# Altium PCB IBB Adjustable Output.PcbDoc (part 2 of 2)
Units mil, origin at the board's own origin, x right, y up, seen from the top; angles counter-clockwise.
Board outline 3000 x 2700 mil, 4 copper layers (Top Layer, Signal Layer 1, Signal Layer 2, Bottom Layer), stack 61.2 mil thick; 75 components, 28 nets, 136 pads, 154 vias.
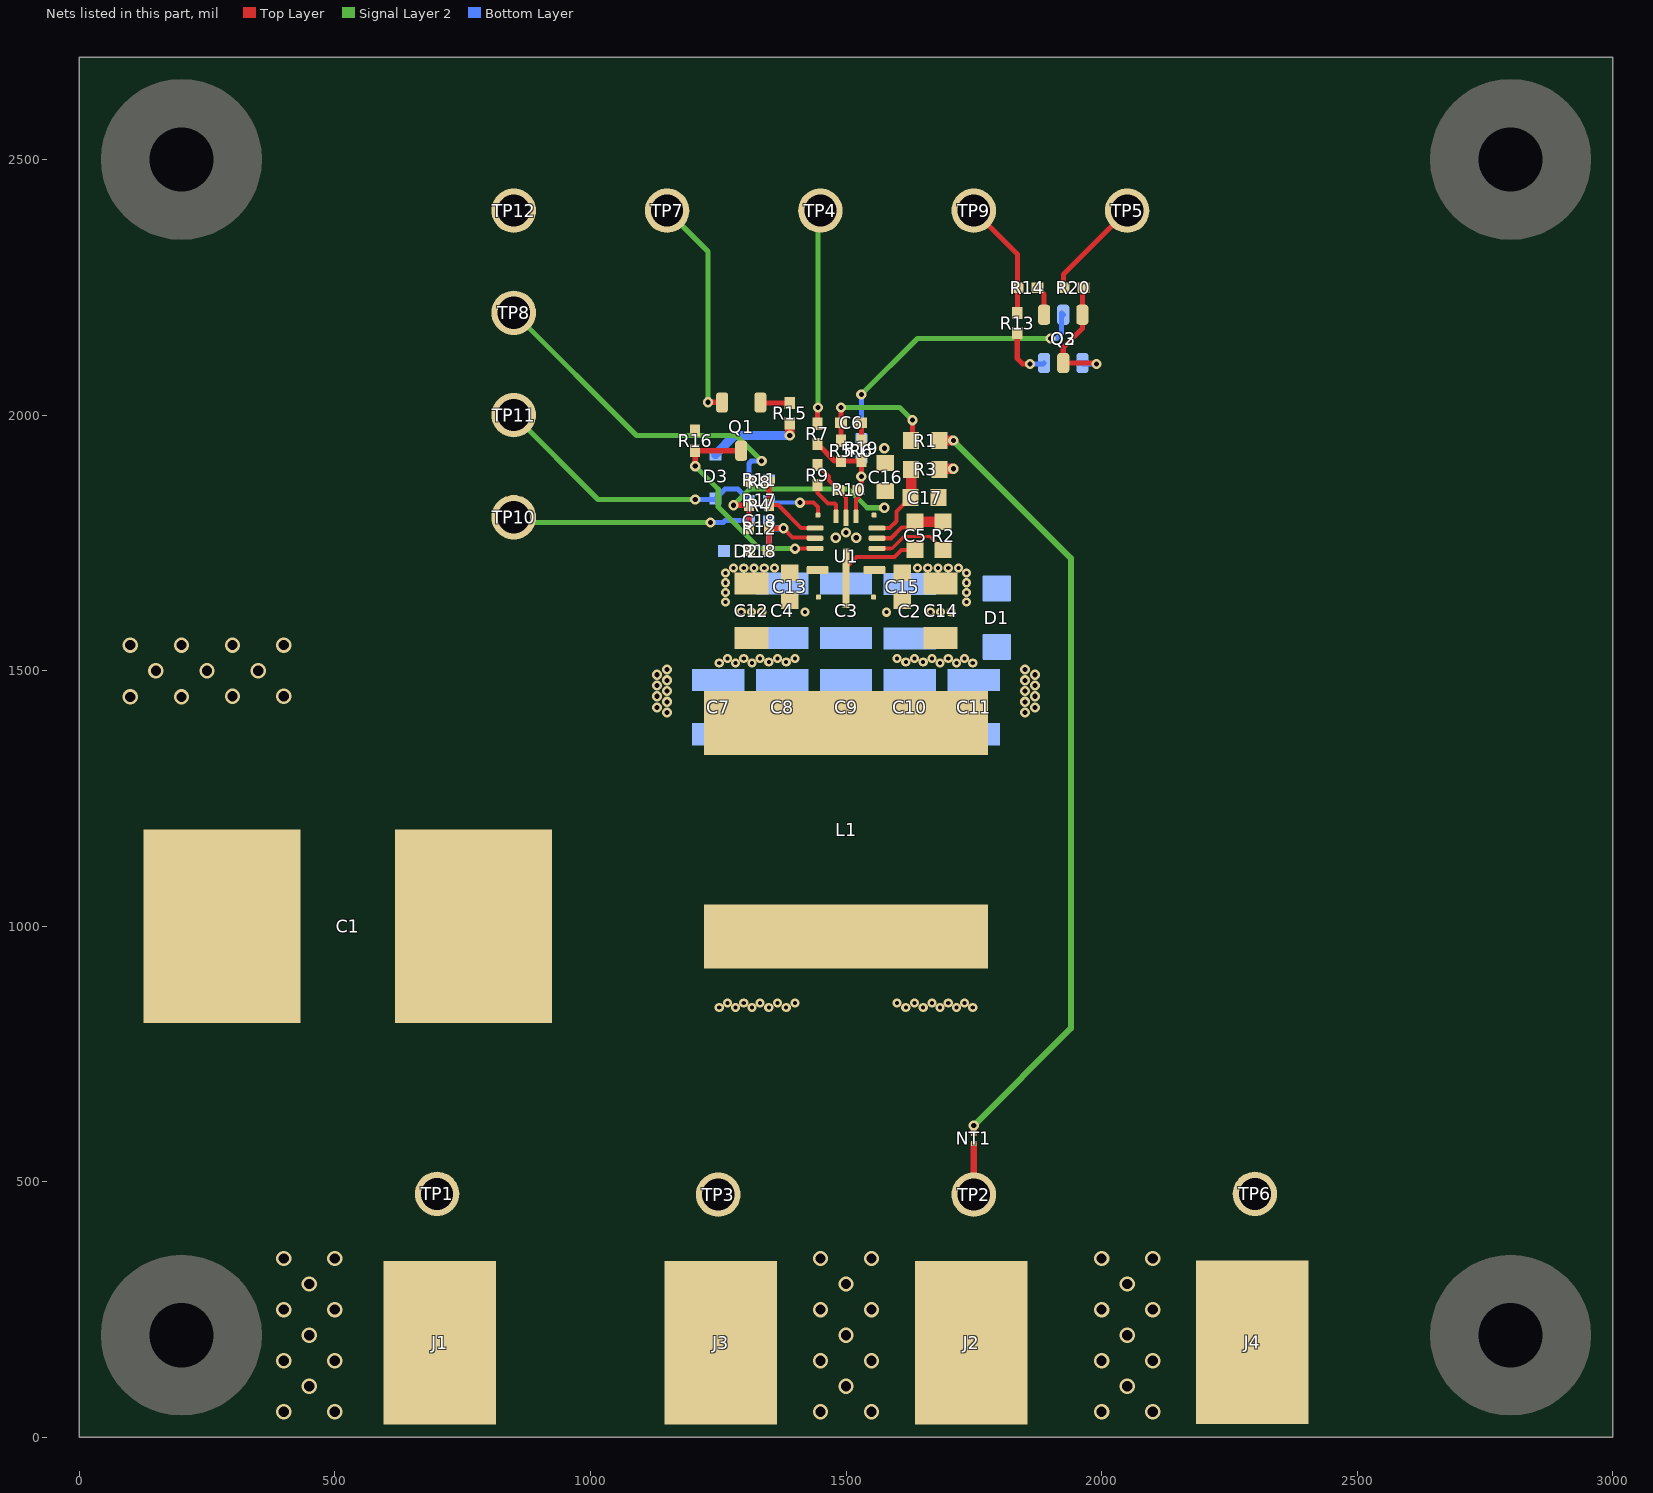
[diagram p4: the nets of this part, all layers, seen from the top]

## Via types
v1: diameter 18, hole 8, Top Layer to Bottom Layer, tented both sides, 66 vias
v2: diameter 20, hole 10, Top Layer to Bottom Layer, tented both sides, 44 vias
v3: diameter 30, hole 20, Top Layer to Bottom Layer, 44 vias

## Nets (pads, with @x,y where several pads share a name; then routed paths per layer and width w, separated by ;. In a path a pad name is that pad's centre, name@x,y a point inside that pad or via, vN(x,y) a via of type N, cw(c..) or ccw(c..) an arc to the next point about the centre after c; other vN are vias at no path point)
+Vin: C1.1 C2.1 C3.1 C4.1 C12.1 C13.1 C14.1 C15.1 J1.1 TP1.1 U1.2 U1.14
  other v1: 1264,1634 1736,1634 1264,1653 1736,1653 1264,1672 1736,1672 1264,1691 1736,1691 1280,1701 1300,1701 1320,1701 1340,1701 1360,1701 1640,1701 1660,1701 1680,1701 1700,1701 1720,1701
  other v3: 400,50 500,50 450,100 400,150 500,150 450,200 400,250 500,250 450,300 400,350 500,350 100,1448.66 200,1448.66 300,1450 400,1450 150,1500 250,1500 350,1500 100,1550 200,1550 300,1550 400,1550
-Vout: C7.2 C8.2 C9.2 C10.2 C11.2 C12.2 C13.2 C14.2 C15.2 C16.2 C17.2 D1.2 D2.2 J4.1 R8.1 R9.1 R10.1 R16.1 R18.1 TP6.1 U1.1 U1.8 U1.15 | length 126.5
  Top Layer w8: R9.1@1444.19,1902.28 1466.73,1879.74 1466.73,1872.25 R10.1@1485.32,1853.66 1500,1838.98 U1.8@1500,1798.9
  other v1: 1579.33,1614.33 1295,1615 1315,1615 1335,1615 1420,1615 1665,1615 1685,1615 1705,1615
  other v2: 1150,1418 1850,1418 1130,1428 1870,1428 1150,1439 1850,1439 1130,1450 1870,1450 1150,1460 1850,1460 1130,1471 1870,1471 1150,1481 1850,1481 1130,1492 1870,1492 1150,1502 1850,1502 1480,1760 1520,1760 1500,1770 1575,1935
  other v3: 2000,50 2100,50 2050,100 2000,150 2100,150 2050,200 2000,250 2100,250 2050,300 2000,350 2100,350
BIAS: C17.1 R3.1 U1.5 | length 157
  Top Layer w8: U1.5@1560.55,1778.7 1585.04,1778.7 1598.6,1792.26 1598.6,1811.04 C17.1@1626.22,1838.66 C17.1@1627.44,1839.88
  Top Layer w20: C17.1@1627.44,1839.88 R3.1@1627.44,1893.66
CBOOT: C5.2 R2.2 U1.4 | length 142.8
  Top Layer w8: U1.4@1560.55,1759.02 1587.99,1759.02 1608.98,1780 1623.78,1780 C5.2@1635,1791.22
  Top Layer w20: C5.2@1635,1791.22 R2.2@1690,1791.22
EN: Q1.2 TP7.1 | length 435.9
  Top Layer w10: v2(1230,2025) 1257.28,2025 Q1.2@1257.6,2024.68
  Signal Layer 2 w10: TP7.1@1150,2400 1230,2320 v2(1230,2025)
EN_IC: Q1.3 R16.2 U1.13 | length 442.3
  Top Layer w8: v2(1400,1738.66) 1400.67,1739.33 U1.13@1439.45,1739.33
  Top Layer w10: v2(1205,1900) R16.2@1205,1930.2 Q1.3@1295,1930.2
  Signal Layer 2 w10: v2(1205,1900) 1250,1855 1250,1820 1331.34,1738.66 v2(1400,1738.66)
"Ext CLK": C18.1 TP10.1 | length 466
  Signal Layer 2 w10: TP10.1@850,1800 860,1790 v2(1235,1790)
  Bottom Layer w10: v2(1235,1790) 1260,1790 1263.66,1793.66 C18.1@1310.32,1793.66
FB: R5.1 R6.1 R7.1 R10.2 R19.1 U1.7 | length 247.7
  Top Layer w8: U1.7@1519.68,1801.85 1519.68,1834.88 1524.69,1839.88 R10.2@1524.69,1853.66 R10.2@1530,1858.98
  Top Layer w10: R7.1@1444.19,1943.66 1477.53,1910.32 R5.1@1490,1910.32 R6.1@1530,1910.32 v2(1530,1880) R10.2@1530,1858.98
  Bottom Layer w10: v2(1530,1880) R19.1@1530,1915.32
GND: C1.2 C2.2 C3.2 C4.2 C7.1 C8.1 C9.1 C10.1 C11.1 D1.1 D3.2 J2.1 J3.1 L1.2 NT1.2 R3.2 R15.1 R20.1 TP2.1 TP3.1 TP5.1 TP12.1 | length 514.8
  Top Layer w10: R20.1@1925.32,2249.02 1925.32,2275.32 TP5.1@2050,2400
  Top Layer w12: TP2.1@1750,475 NT1.2@1750,575
  Top Layer w18: v2(1390,1960) R15.1@1390,1983.98
  Top Layer w20: R3.2@1682.56,1893.66 1683.9,1895 v2(1710,1895)
  Bottom Layer w18: D3.2@1245,1923.31 1281.69,1960 v2(1390,1960)
  other v1: 1252,841 1284,841 1316,841 1349,841 1383,841 1617,841 1651,841 1684,841 1716,841 1748,841 1268,850 1300,850 1332,850 1366,850 1400,850 1600,850 1634,850 1668,850 1700,850 1732,850 1252,1515 1284,1515 1316,1515 1684,1515 1716,1515 1748,1515 1349,1517 1383,1517 1617,1517 1651,1517 1268,1524 1300,1524 1332,1524 1366,1524 1400,1524 1600,1524 1634,1524 1668,1524 1700,1524 1732,1524
  other v3: 1450,50 1550,50 1500,100 1450,150 1550,150 1500,200 1450,250 1550,250 1500,300 1450,350 1550,350
NetC6_1: C6.1 R1.1 R5.2 | length 256.7
  Top Layer w10: R5.2@1490,1949.69 v2(1490,2015) ; R1.1@1627.44,1950 1630,1952.56 v2(1630,1990)
  Signal Layer 2 w10: v2(1490,2015) 1605,2015 v2(1630,1990)
NetC6_2: C6.2 R6.2 | length 35.4
  Top Layer w10: C6.2@1529.69,1985 1530,1984.69 R6.2@1530,1949.69
NetNT1_1: NT1.1 R1.2 | length 1556.4
  Top Layer w12: NT1.1@1750,595 v2(1750,610)
  Top Layer w20: R1.2@1682.56,1950 v2(1710,1950)
  Signal Layer 2 w12: v2(1710,1950) 1940,1720 1940,800 v2(1750,610)
NetQ1_1: Q1.1 R15.2 | length 58.2
  Top Layer w10: Q1.1@1332.4,2024.68 1333.74,2023.35 R15.2@1390,2023.35
NetQ2_1: Q2.1 Q3.1 Q3.3 R20.2 | length 257.7
  Top Layer w10: R20.2@1964.69,2249.02 1962.4,2246.73 Q3.1@1962.4,2196.26 1962.4,2169.61 1925,2132.21 Q3.3@1925,2101.77 1988.23,2101.77 v2(1990,2100)
  Bottom Layer w10: Q2.1@1962.4,2101.77 1964.17,2100 v2(1990,2100)
NetQ2_2: Q2.2 R13.1 | length 107.4
  Top Layer w10: R13.1@1835,2160.31 1835,2110.75 1845.75,2100 v2(1860,2100)
  Bottom Layer w10: v2(1860,2100) 1885.83,2100 Q2.2@1887.6,2101.77
NetQ2_3: Q2.3 R19.2 | length 571.1
  Signal Layer 2 w10: v2(1530,2040) 1640,2150 v2(1900,2150)
  Bottom Layer w10: R19.2@1530,1954.68 v2(1530,2040) ; v2(1900,2150) 1911.58,2150 1921.58,2160 1921.58,2199.69 Q2.3@1925,2196.26
NetQ3_2: Q3.2 R14.1 | length 58.1
  Top Layer w10: R14.1@1874.69,2249.02 1887.6,2236.1 Q3.2@1887.6,2196.26
NetR2_1: R2.1 U1.3 | length 150.2
  Top Layer w6: 1586.19,1739.33 1590.37,1739.33 1613.76,1762.72 1663.38,1762.72 R2.1@1690,1736.1
  Top Layer w8: U1.3@1560.55,1739.33 1586.19,1739.33
NetR4_2: R4.2 R8.2 U1.11 | length 153.4
  Top Layer w8: R4.2@1349.68,1823.66 1367.46,1823.66 1412.42,1778.7 U1.11@1439.45,1778.7
  Top Layer w10: R4.2@1349.68,1823.66 R8.2@1349.69,1868.66
Pgood: D3.1 R17.1 TP11.1 | length 545.8
  Signal Layer 2 w10: TP11.1@850,2000 1015,1835 v2(1205,1835)
  Bottom Layer w10: v2(1205,1835) 1243.31,1835 D3.1@1245,1836.69 1263.31,1855 1288.98,1855 R17.1@1310.32,1833.66
RESET!: R11.1 R17.2 U1.10 | length 156.5
  Top Layer w8: v2(1410,1828.66) 1436.12,1828.66 1444.88,1819.9 U1.10@1444.88,1804.29
  Bottom Layer w8: R11.1@1349.68,1873.66 R17.2@1349.69,1833.66 1354.69,1828.66 v2(1410,1828.66)
RT: R9.2 U1.9 | length 83.8
  Top Layer w8: R9.2@1444.19,1862.91 1444.19,1847.47 1464.66,1826.99 1477.89,1826.99 1480.32,1824.56 U1.9@1480.32,1801.85
SW: C5.1 L1.1 U1.16 | length 170.2
  Top Layer w8: U1.16@1500,1680.75 1500,1701.72 1520.81,1722.54 1594.89,1722.54 1608.45,1736.1 C5.1@1635,1736.1
SYNC/MODE: C18.2 D2.1 R12.1 R18.2 U1.12 | length 232.2
  Top Layer w8: v2(1377.48,1778.66) 1395.61,1760.54 1439.45,1760.54 U1.12@1439.45,1759.02
  Top Layer w10: R18.2@1349.69,1733.66 R12.1@1349.68,1778.66 v2(1377.48,1778.66)
  Bottom Layer w8: D2.1@1348.31,1733.66 D2.1@1349.69,1735.04
  Bottom Layer w12: D2.1@1349.69,1735.04 1349.69,1778.66 ; C18.2@1349.69,1793.66 1349.69,1778.66 ; v2(1377.48,1778.66) 1349.69,1778.66
VCC: C16.1 R4.1 R12.2 U1.6 | length 398.3
  Top Layer w10: v2(1280,1823.66) R4.1@1310.32,1823.66 R12.2@1310.32,1778.66
  Signal Layer 2 w10: v2(1280,1823.66) 1311.34,1855 1505,1855 1541.34,1818.66 v2(1575,1818.66)
Vcntl1: R7.2 TP4.1 | length 419.4
  Top Layer w10: R7.2@1444.19,1983.03 1444.19,2014.19 v2(1445,2015)
  Signal Layer 2 w10: v2(1445,2015) 1445,2395 TP4.1@1450,2400
Vcntl2: R13.2 R14.2 TP9.1 | length 235.8
  Top Layer w10: TP9.1@1750,2400 1835.32,2314.68 R14.2@1835.32,2249.02 1835.32,2200 R13.2@1835,2199.69
Vpullup: R11.2 TP8.1 | length 663.4
  Signal Layer 2 w10: TP8.1@850,2200 1090,1960 1285,1960 v2(1335,1910)
  Bottom Layer w10: R11.2@1310.31,1873.66 1310.31,1905.31 1315,1910 v2(1335,1910)
pads on no net: H1.1 H2.1 H3.1 H4.1 H5.0 H6.0 H7.0 H8.0 LBL1.0

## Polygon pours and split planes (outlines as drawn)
VCC on Top Layer "TOP_LAYER_VCC" (solid, remove dead copper, pour order 0): 1535,1795 1575,1795 1595,1815 1595,1870 1560,1870 1560,1845 1535,1820
+Vin on Top Layer "TOP_LAYER_+Vin_IC_Left" (solid, remove dead copper, pour order 2): 1535,1710 1535,1685 1575,1685 1590,1670 1625,1670 1647,1648 1720,1648 1720,1636 1731,1625 1740,1625 1750,1635 1750,1690 1730,1710
+Vin on Top Layer "TOP_LAYER_+Vin_IC_Left" (solid, remove dead copper, pour order 1): 1465,1710 1465,1685 1425,1685 1410,1670 1375,1670 1353,1648 1280,1648 1280,1637 1268,1625 1259,1625 1253,1631 1253,1693 1270,1710
-Vout on Top Layer "TOP_LAYER_-Vout" (solid, remove dead copper, pour order 6): 1950,0 1950,1380 590,1380 590,1630 0,1630 0,2700 3000,2700 3000,0
+Vin on Top Layer "TOP_LAYER_+Vin" (solid, remove dead copper, pour order 4): 850,0 850,430 470,810 470,1600 0,1600 0,0
GND on Top Layer "TOP_LAYER_GND" (solid, remove dead copper, pour order 5): 950,1350 1050,1250 1050,875 1215,875 1215,1050 1785,1050 1785,875 1900,875 1900,0 900,0 900,500 590,810 590,1350
SW on Top Layer "TOP_LAYER_SW" (solid, remove dead copper, pour order 3): 1220,1463.66 1370,1463.66 1490,1583.66 1490,1643.66 1510,1643.66 1510,1583.66 1630,1463.66 1780,1463.66 1780,1333.66 1220,1333.66
GND on Bottom Layer "BOTTOM_LAYER_GND" (solid, remove dead copper, pour order 14): 1795,0 1795,865 1205,865 1205,0
-Vout on Bottom Layer "BOTTOM_LAYER_-Vout" (solid, remove dead copper, pour order 16): 0,0 0,2700 3000,2700 3000,0
+Vin on Bottom Layer "BOTTOM_LAYER_+Vin" (solid, remove dead copper, pour order 11): 1280,1645 1280,1635 1271,1626 1259,1626 1250,1635 1250,1690 1270,1710 1730,1710 1750,1690 1750,1636 1740.01,1626.01 1729.99,1626.01 1720,1636 1720,1645
GND on Bottom Layer "BOTTOM_LAYER_GND" (solid, remove dead copper, pour order 12): 1297.49,1585 1237.49,1525 1195,1525 1195,1435 1795,1435 1825,1465 1825,1575 1765,1575 1745,1555 1725,1555 1695,1585
GND on Signal Layer 2 "SIGNAL_LAYER_2_GND" (solid, remove dead copper, pour order 10): 0,0 0,2700 3000,2700 3000,0
+Vin on Signal Layer 2 "SIGNAL_LAYER_2_+Vin" (solid, remove dead copper, pour order 9): 1785,955 1700,870 1245,870 1140,765 1140,527.8 1140,0 0,0 0,1710 1730,1710 1785,1655
GND on Signal Layer 1 "SIGNAL_LAYER_1_GND" (solid, remove dead copper, pour order 7): 1205,1540 1795,1540 1795,815 1205,815
-Vout on Signal Layer 1 "SIGNAL_LAYER_1_-Vout" (solid, remove dead copper, pour order 8): 0,0 0,2700 3000,2700 3000,0

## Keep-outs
Keep-Out Layer:
  text ".Layer_Name" at 577,-858.49 h60

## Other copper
Top Layer:
  pour cut-out: 1510,1740 1535,1740 1535,1730 1510,1730
  pour cut-out: 1485,1740 1485,1720 1465,1720 1465,1740
  pour cut-out: 1360,1470 1395,1505 1165,1505 1165,875 1215,875 1215,1050 1785,1050 1785,875 1830,875 1830,1505 1605,1505 1640,1470 1785,1470 1785,1325 1215,1325 1215,1470
  text ".Layer_Name" at 577,-858.49 h60
Bottom Layer:
  text ".Layer_Name" at 577,-858.49 h60

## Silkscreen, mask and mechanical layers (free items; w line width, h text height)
Top Overlay:
  text "'.PRJ_Number'.PCB_Rev" at 450,2550 h108.27
  text ".Layer_Name" at 577,-858.49 h60
Bottom Overlay:
  text ".Layer_Name" at 577,-858.49 h60
Top Paste:
  text ".Layer_Name" at 577,-858.49 h60
Bottom Paste:
  text ".Layer_Name" at 577,-858.49 h60
Top Solder:
  text ".Layer_Name" at 577,-858.49 h60
  text ".Layer_Name" at 577,-858.49 h60
Bottom Solder:
  text ".Layer_Name" at 577,-858.49 h60
Drill Guide:
  text ".Layer_Name" at 577,-858.49 h60
M1 Board Outline:
  the board outline again, w10
  text ".Layer_Name" at 577,-858.49 h60
M2 Board Dimensions:
  rectangle: 125,-400 500,-275
  rectangle: 0,-275 125,-150
  lines w7: 0,-275 1000,-275 ; 125,-400 125,-150 ; 250,-400 250,-150 ; 500,-400 500,-150 ; 750,-400 750,-150 ; 0,-400 0,-150 1000,-150 1000,-400 0,-400
  text ".Layer_Name" at 577,-858.49 h60
M3 3D STEP Top:
  text ".Layer_Name" at 577,-858.49 h60
M4 3D STEP Bottom:
  text ".Layer_Name" at 577,-858.49 h60
M5 Assembly Top:
  lines w10: -292,-930.17 6308,-930.17 ; -292,-726.83 6310,-726.83 ; -292,-523.5 -292,-1133.5 3713,-1133.5 6310,-1133.5 6310,-523.5 -291.5,-523.5 -291.5,-1133.5 1284,-1133.5 ; 2173,-1133.5 2173,-523.5 ; 3440,-726.83 3440,-523.5 ; 4280,-726.83 4280,-523.5 ; 4902,-1140 4902,-937.17
  text "COMPONENTS MARKED 'DNP' SHOULD NOT BE POPULATED." at 1153.5,-318.5 h60
  text "ASSEMBLY VARIANT:" at 1153,-434 h60
  text ".VariantName" at 2189,-434 h60
  text "PCB VIEWED FROM TOP SIDE" at -228.5,-655.67 h60
  text "BOARD #:" at 2248,-655.67 h60
  text ".PRJ_Number" at 2793.5,-655.67 h60
  text "REV:" at 3638,-655.67 h60
  text ".PCB_Rev" at 3929.5,-655.67 h60
  text "SVN REV:" at 4476,-655.67 h60
  text ".VersionControl_RevNumber" at 4982,-655.67 h60
  text "PLOT NAME =" at -228.5,-1064.34 h60
  text ".plot_File_Name" at 577,-1064.34 h60
  text "GENERATED    :" at 2250,-1064.34 h60
  text ".Print_Date" at 3119.5,-1064.34 h60
  text ".Print_Time" at 3848.5,-1064.34 h60
  text "TEXAS INSTRUMENTS" at 5113,-1064.34 h60
M6 Assembly Bottom:
  lines w10: -292.5,-727.33 6309.5,-727.33 ; -290.5,-930.67 6309.5,-930.67 ; 1115.5,-1140.5 1115.5,-937.67 ; 1737.5,-727.33 1737.5,-524 ; 2577.5,-727.33 2577.5,-524 ; 3844.5,-1134 3844.5,-524 ; 4733.5,-1134 6309,-1134 6309,-524 -292.5,-524 -292.5,-1134 2304.5,-1134 6309.5,-1134 6309.5,-524
  text "COMPONENTS MARKED 'DNP' SHOULD NOT BE POPULATED." at 6102,-318 h60
  text ".VariantName" at 5058,-434 h60
  text "ASSEMBLY VARIANT:" at 6097,-434 h60
  text ".VersionControl_RevNumber" at 1035.5,-656.17 h60
  text "SVN REV:" at 1541.5,-656.17 h60
  text ".PCB_Rev" at 2088,-656.17 h60
  text "REV:" at 2379.5,-656.17 h60
  text ".PRJ_Number" at 3224,-656.17 h60
  text "BOARD #:" at 3769.5,-656.17 h60
  text "PCB VIEWED FROM BOTTOM SIDE" at 6246,-656.17 h60
  text "TEXAS INSTRUMENTS" at 904.5,-1064.84 h60
  text ".Print_Time" at 2169,-1064.84 h60
  text ".Print_Date" at 2898,-1064.84 h60
  text "GENERATED    :" at 3767.5,-1064.84 h60
  text ".plot_File_Name" at 5440.5,-1064.84 h60
  text "PLOT NAME =" at 6246,-1064.84 h60
M9 Title Sheet:
  drawing of 56 lines, arcs and shapes, not listed
  text "1" at 1058.34,13381.39 h70
  text "2" at 4384,13381.39 h70
  text "3" at 7714,13381.39 h70
  text "4" at 11049,13381.39 h70
  text "5" at 14374,13381.39 h70
  text "6" at 17709,13381.39 h70
  text "A" at -463,11603.39 h70
  text "A" at 19237,11603.39 h70
  text "B" at -463,7853.39 h70
  text "B" at 19237,7853.39 h70
  text "C" at -463,4103.39 h70
  text "C" at 19237,4103.39 h70
  text "D" at -463,353.39 h70
  text "D" at 19237,353.39 h70
  text "PROJECT TITLE:" at 16143,268.39 h45
  text ".PRJ_Title" at 16193,135.06 h70
  text "DESIGNED FOR:" at 16143,-32.61 h45
  text ".PRJ_Customer" at 16193,-172.61 h70
  text "FILE NAME:" at 16143,-332.61 h45
  text ".PCB_File_Name_No_Path" at 16193,-452.61 h70
  text "Texas Instruments (TI) and/or its licensors do not warrant the accuracy or completeness of this specification" at 11173.5,-614.45 h45
  text "ENGINEER:" at 16143,-622.61 h45
  text "LAYOUT BY:" at 17648,-622.61 h45
  text "or any information contained therein. TI and/or its licensors do not warrant that this design will meet" at 11128.51,-727.11 h45
  text ".PRJ_Engineer" at 16193,-777.6 h70
  text ".PCB_Layout" at 17698.5,-777.6 h70
  text "the specifications, will be suitable for your application or fit for any particular purpose, or will operate in" at 11128.51,-839.78 h45
  text ".Layer_Name" at 577,-858.49 h60
  text "ALTIUM DESIGNER VERSION:" at 17648,-932.61 h45
  text "an implementation. TI and/or its licensors do not warrant that the design is production worthy. You should" at 11128.51,-952.44 h45
  text "completely validate and test your design implementation to confirm the system functionality for your application." at 11173.5,-1065.11 h45
  text ".print_Scale" at 16193,-1065.94 h70
  text ".Application_BuildNumber" at 17698.5,-1065.94 h70
  text "1" at 1058.34,-1318.61 h70
  text "2" at 4384,-1318.61 h70
  text "3" at 7714,-1318.61 h70
  text "4" at 11049,-1318.61 h70
  text "5" at 14374,-1318.61 h70
  text "6" at 17709,-1318.61 h70
M10 Fab Notes:
  drawing of 189 lines, arcs and shapes, not listed
  text "DESIGN INFORMATION" at 17178.02,6365.17 h60
  text "MIN. TRACK WIDTH:" at 16533.46,6233.05 h60
  text "6" at 17629.7,6233.05 h60
  text "MIL" at 17784.46,6233.05 h60
  text "MIN. CLEARANCE:" at 16533.46,6108.92 h60
  text "MIL" at 17784.46,6108.92 h60
  text "7.874" at 17459.65,6104.33 h60
  text "MIN. VIA PAD SIZE:" at 16533.46,5984.8 h60
  text "18" at 17599.71,5984.8 h60
  text "MIL" at 17784.46,5984.8 h60
  text "0.127mm (5MIL)" at 17228.46,5854.9 h60
  text "MINIMUM ANNULAR RING" at 16204.23,5846.67 h60
  text "EXTERNAL" at 17936.46,5846.67 h60
  text "PER" at 16404.23,5736.55 h60
  text "IPC-D-275 CLASS 2 LEVEL C" at 16624.23,5736.54 h60
  text "MIL, HOLES" at 18112.46,5636.07 h60
  text "+/-" at 17720,5627.48 h60
  text "+/-" at 18574,5627.48 h60
  text "REGISTRATION TOLERANCES:" at 16204.23,5626.42 h60
  text "METAL" at 17404,5626.42 h60
  text "5" at 17980.2,5626.42 h60
  text "3" at 18813.2,5626.42 h60
  text "MIL" at 18929.46,5626.42 h60
  text "HOLE SIZE TOLERANCE (UNLESS OTHERWISE SPECIFIED):" at 16204.23,5528.1 h60
  text "+/-" at 18574,5525.23 h60
  text "3" at 18813.2,5524.17 h60
  text "MIL" at 18929.46,5524.17 h60
  text "MATERIAL:" at 16129.46,5386.52 h60
  text "FR-4 High Tg" at 17115.9,5258 h60
  text "X" at 16971.46,5250.01 h60
  text "FR-408" at 16550.46,5245.49 h60
  text "OTHER" at 18038.46,5245.49 h60
  text "62 MIL (1.6mm) +/-10%" at 16870.56,5102.46 h60
  text "X" at 16750.46,5100.01 h60
  text "THICKNESS:" at 16204.23,5094.24 h60
  text "OTHER" at 18155.46,5094.24 h60
  text "TOLERANCE:" at 16204.23,4955.92 h60
  text "X" at 17052.46,4955.92 h60
  text "ANSI IPC-6012 TYPE 3 CLASS 2" at 17230.48,4955.92 h60
  text "OTHER +/-" at 17230.46,4811.73 h60
  text "BOW & TWIST:" at 16204.23,4666.54 h60
  text "X" at 17052.46,4666.54 h60
  text "ANSI IPC-6012 TYPE 3 CLASS 2" at 17230.48,4666.54 h60
  text "OTHER +/-" at 17230.46,4519.85 h60
  text "DRILLING:" at 16129.46,4389.23 h60
  text "NC_DRILL FILES" at 17890.46,4284.04 h60
  text "REFERENCE:" at 16204.23,4280.1 h60
  text "X" at 16861.46,4280.01 h60
  text "AS SHOWN" at 17039.46,4280.1 h60
  text "X" at 17762.46,4280.1 h60
  text "OTHER" at 18188.46,4137.85 h60
  text "PTH COPPER THICKNESS:" at 16203.91,4134.32 h60
  text "X" at 17343.14,4134.32 h60
  text "20-30 um" at 17471.14,4134.32 h60
  text "BOARD FINISH:" at 16129.46,3986.73 h60
  text "SILKSCREEN:" at 16284.68,3876.6 h60
  text "X" at 17242.46,3876.6 h60
  text "TOP" at 17359.46,3876.6 h60
  text "X" at 17752.46,3876.6 h60
  text "BOTTOM" at 17870.46,3876.6 h60
  text "SILKSCREEN COLOR:" at 16284.68,3721.41 h60
  text "X" at 17241.46,3721.41 h60
  text "WHITE" at 17359.46,3721.41 h60
  text "OTHER" at 17870.46,3721.41 h60
  text "X" at 17372.46,3577.96 h60
  text "GREEN" at 17490.46,3577.96 h60
  text "OTHER" at 18108.46,3577.96 h60
  text "SOLDER RESIST COLOR:" at 16284.68,3571.1 h60
  text "X" at 17372.46,3423.71 h60
  text "MATTE" at 17490.46,3423.71 h60
  text "SEMI-GLOSS" at 18108,3423.07 h60
  text "IMMERSION GOLD (ENIG)" at 17190.46,3250.94 h60
  text "ENEPIG" at 18528,3243.72 h60
  text "SURFACE FINISH:" at 16129.46,3242.72 h60
  text "X" at 17012.46,3242.72 h60
  text "IMM. TIN/SILVER OR EQUIV" at 16459,3105.4 h60
  text "OTHER" at 17890.46,3101.47 h60
  text "ARRAY/PANEL:" at 16129.46,2946.09 h60
  text "X" at 17012.46,2940 h60
  text "CUT AND TRIM PER M1 BOARD OUTLINE" at 17190.46,2937.87 h60
  text "N.C. ROUTE" at 17190.46,2801.9 h60
  text "V. SCORE" at 18056.46,2801.9 h60
  text "CERTIFICATION:" at 16129.46,2672.77 h60
  text "MATERIALS AND WORKMANSHIP FOR ALL PCBS" at 16854.46,2672.77 h60
  text "TO MEET OR EXCEED THE REQUIREMENTS OF:" at 16854.46,2578.71 h60
  text "X" at 16491.97,2450.08 h60
  text "ANSI IPC-A-600F CLASS ->" at 16619.96,2450.08 h60
  text "X" at 18267.97,2450.08 h60
  text "2" at 18377.96,2450.08 h60
  text "1" at 18062.96,2448.58 h60
  text "3" at 18731.96,2448.58 h60
  text "X" at 17303.97,2302.39 h60
  text "RoHS" at 17431.96,2302.39 h60
  text "OTHER" at 18076.36,2302.39 h60
  text "PER ORDER" at 18473.42,2302.39 h60
  text "ALL BOARDS MUST MEET OR EXCEED UL94-V0 REQUIREMENTS." at 16157,2148.57 h60
  text "PCB MUST BEAR THE UL94V-0 UL REGISTERED MATERIAL ID NUMBER" at 16157,2032.5 h60
  text "ADDITIONAL REQUIREMENTS:" at 16129.46,1863.08 h60
  text "MICROSECTION:" at 16204.23,1755.95 h60
  text "YES" at 17109.96,1755.95 h60
  text "REQUIRED" at 17971.46,1611.62 h60
  text "BARE BOARD ELEC. TEST:" at 16204.23,1608.76 h60
  text "NONE" at 17509.96,1608.76 h60
  text "X" at 17853.46,1608.76 h60
  text "PER ORDER" at 18563.46,1608.76 h60
  text "XX MIL VIAS REQUIRE NON-CONDUCTIVE FILL AND PLANARIZE" at 16372.38,1403.82 h59
  text "XX MIL VIAS REQUIRE CONDUCTIVE FILL AND PLANARIZE" at 16380.38,1299.84 h60
  text "OUTER XX MIL TRACES REQUIRE 50 OHM SINGLE-ENDED IMPEDANCE" at 16379.39,1136.46 h58
  text "LAYER 2 & 3 (INNER LAYERS) XX MIL WIDE, XX MIL SPACE / TRACES REQUIRE 100 OHM DIFFERENTIAL IMPEDANCE" at 16371.39,900.74 h60
  text ".Layer_Name" at 577,-858.49 h60
M11 Gerber Information:
  lines w10: -292,-930.17 6308,-930.17 ; -292,-726.83 6310,-726.83 ; -292,-523.5 -292,-1133.5 3713,-1133.5 6310,-1133.5 6310,-523.5 -291.5,-523.5 -291.5,-1133.5 1284,-1133.5 ; 2173,-1133.5 2173,-523.5 ; 3440,-726.83 3440,-523.5 ; 4280,-726.83 4280,-523.5 ; 4902,-1140 4902,-937.17
  text "ALL ARTWORK VIEWED FROM TOP SIDE" at -228.5,-655.67 h60
  text "BOARD #:" at 2248,-655.67 h60
  text ".PRJ_Number" at 2793.5,-655.67 h60
  text "REV:" at 3638,-655.67 h60
  text ".PCB_Rev" at 3929.5,-655.67 h60
  text "SVN REV:" at 4476,-655.67 h60
  text ".VersionControl_RevNumber" at 4982,-655.67 h60
  text "LAYER NAME =" at -228.5,-858.49 h60
  text "PLOT NAME =" at -228.5,-1064.34 h60
  text ".plot_File_Name" at 577,-1064.34 h60
  text "GENERATED    :" at 2250,-1064.34 h60
  text ".Print_Date" at 3119.5,-1064.34 h60
  text ".Print_Time" at 3848.5,-1064.34 h60
  text "TEXAS INSTRUMENTS" at 5113,-1064.34 h60
M12 Stackup:
  drawing of 295 lines, arcs and shapes, not listed
  text "Layer" at 14595.06,12911.48 h60
  text "Name" at 15004.97,12911.48 h60
  text "Material" at 15944.71,12911.48 h60
  text "Thickness" at 16804.48,12911.48 h60
  text "Constant" at 17454.32,12911.48 h60
  text "Board Layer Stack" at 18024.18,12911.48 h60
  text "1" at 14595.06,12791.48 h60
  text "Top Overlay" at 15004.97,12791.48 h60
  text "2" at 14595.06,12671.48 h60
  text "Top Solder" at 15004.97,12671.48 h60
  text "Solder Resist" at 15944.71,12671.48 h60
  text "0.40mil" at 16804.48,12671.48 h60
  text "3.5" at 17454.32,12671.48 h60
  text "3" at 14595.06,12551.48 h60
  text "Top Layer" at 15004.97,12551.48 h60
  text "Copper" at 15944.71,12551.48 h60
  text "1.40mil" at 16804.48,12551.48 h60
  text "4" at 14595.06,12431.48 h60
  text "Dielectric 2" at 15004.97,12431.48 h60
  text "12.30mil" at 16804.48,12431.48 h60
  text "4.2" at 17454.32,12431.48 h60
  text "5" at 14595.06,12311.48 h60
  text "Signal Layer 1" at 15004.97,12311.48 h60
  text "Copper" at 15944.71,12311.48 h60
  text "1.40mil" at 16804.48,12311.48 h60
  text "6" at 14595.06,12191.48 h60
  text "Dielectric 3" at 15004.97,12191.48 h60
  text "31.00mil" at 16804.48,12191.48 h60
  text "4.2" at 17454.32,12191.48 h60
  text "7" at 14595.06,12071.48 h60
  text "Signal Layer 2" at 15004.97,12071.48 h60
  text "Copper" at 15944.71,12071.48 h60
  text "1.40mil" at 16804.48,12071.48 h60
  text "8" at 14595.06,11951.48 h60
  text "Dielectric1" at 15004.97,11951.48 h60
  text "FR-4 High Tg" at 15944.71,11951.48 h60
  text "12.30mil" at 16804.48,11951.48 h60
  text "4.2" at 17454.32,11951.48 h60
  text "9" at 14595.06,11831.48 h60
  text "Bottom Layer" at 15004.97,11831.48 h60
  text "Copper" at 15944.71,11831.48 h60
  text "1.40mil" at 16804.48,11831.48 h60
  text "10" at 14595.06,11711.48 h60
  text "Bottom Solder" at 15004.97,11711.48 h60
  text "Solder Resist" at 15944.71,11711.48 h60
  text "0.40mil" at 16804.48,11711.48 h60
  text "3.5" at 17454.32,11711.48 h60
  text "11" at 14595.06,11591.48 h60
  text "Bottom Overlay" at 15004.97,11591.48 h60
  text ".Layer_Name" at 577,-858.49 h60
M13 Component Bodies Top:
  text ".Layer_Name" at 577,-858.49 h60
M14 Component Bodies Bottom:
  text ".Layer_Name" at 577,-858.49 h60
M15 Courtyards Top:
  text ".Layer_Name" at 577,-858.49 h60
M16 Courtyards Bottom:
  text ".Layer_Name" at 577,-858.49 h60
Drill Drawing:
  circle w10: c5443.72,2835 r27.63
  lines w10: 5416.09,2931.7 5471.34,2931.7 5471.34,2986.95 5416.09,2986.95 5416.09,2931.7 ; 5416.09,3069.83 5429.9,3069.83 5443.72,3056.02 5457.53,3069.83 5471.34,3069.83 5457.53,3083.64 5471.34,3097.46 5457.53,3097.46 5443.72,3111.27 5429.9,3097.46 5416.09,3097.46 5429.9,3083.64 5416.09,3069.83 ; 5416.09,3235.59 5471.34,3235.59 5443.72,3180.34 5416.09,3235.59 ; 5416.09,3304.66 5443.72,3318.47 5471.34,3304.66 5457.53,3332.28 5471.34,3359.91 5443.72,3346.1 5416.09,3359.91 5429.9,3332.28 5416.09,3304.66
  lines w12: 5366,2770.08 8597.49,2770.08 ; 5366,3391.68 8597.49,3391.68 ; 5703.86,2645.76 5703.86,3516 ; 6035.86,2645.76 6035.86,3516 ; 6672.43,2645.76 6672.43,3516 ; 6931.57,2645.76 6931.57,3516 ; 7306.72,2645.76 7306.72,3516 ; 8031.05,2645.76 8031.05,3516 ; 5366,2645.76 8597.49,2645.76 8597.49,3516 5366,3516 5366,2645.76
  text "Symbol" at 5440.59,3428.98 h72
  text "Quantity" at 5741.16,3428.98 h72
  text "Finished Hole Size" at 6073.16,3428.98 h72
  text "Plated" at 6709.72,3428.98 h72
  text "Hole Type" at 6968.86,3428.98 h72
  text "Drill Layer Pair" at 7344.02,3428.98 h72
  text "Hole Tolerance" at 8068.35,3428.98 h72
  text "66" at 5741.16,3304.66 h60
  text "8.00mil (0.203mm)" at 6073.16,3304.66 h60
  text "PTH" at 6709.72,3304.66 h60
  text "Round" at 6968.86,3304.66 h60
  text "Top Layer - Bottom Layer" at 7344.02,3304.66 h60
  text "44" at 5741.16,3180.34 h60
  text "10.00mil (0.254mm)" at 6073.16,3180.34 h60
  text "PTH" at 6709.72,3180.34 h60
  text "Round" at 6968.86,3180.34 h60
  text "Top Layer - Bottom Layer" at 7344.02,3180.34 h60
  text "44" at 5741.16,3056.02 h60
  text "20.00mil (0.508mm)" at 6073.16,3056.02 h60
  text "PTH" at 6709.72,3056.02 h60
  text "Round" at 6968.86,3056.02 h60
  text "Top Layer - Bottom Layer" at 7344.02,3056.02 h60
  text "12" at 5741.16,2931.7 h60
  text "63.00mil (1.600mm)" at 6073.16,2931.7 h60
  text "PTH" at 6709.72,2931.7 h60
  text "Round" at 6968.86,2931.7 h60
  text "Top Layer - Bottom Layer" at 7344.02,2931.7 h60
  text "4" at 5741.16,2807.38 h60
  text "125.98mil (3.200mm)" at 6073.16,2807.38 h60
  text "PTH" at 6709.72,2807.38 h60
  text "Round" at 6968.86,2807.38 h60
  text "Top Layer - Bottom Layer" at 7344.02,2807.38 h60
  text "170 Total" at 5741.16,2683.06 h60
  text ".Layer_Name" at 577,-858.49 h60
M17 Embedded Cavity:
  text ".Layer_Name" at 577,-858.49 h60
M18 Embedded Assembly:
  text ".Layer_Name" at 577,-858.49 h60
M19 Embedded Keepout:
  text ".Layer_Name" at 567,-858.49 h60

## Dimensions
0,-400 to 1000,-400 on M2 Board Dimensions
0,0 to 3000,0 on M2 Board Dimensions
0,0 to 0,2700 on M2 Board Dimensions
